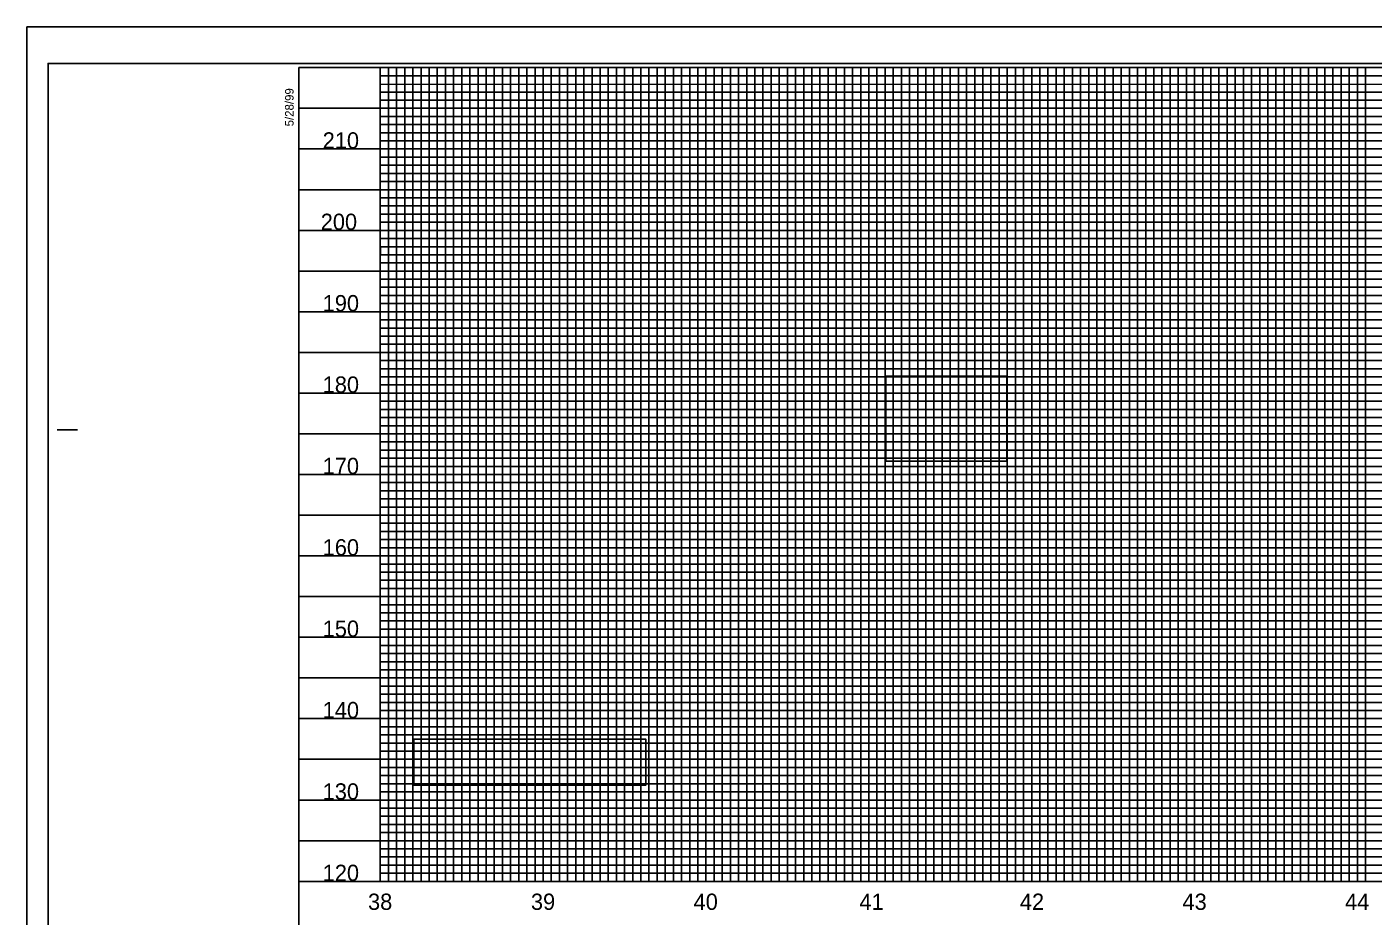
# Model space of a CAD drawing. Extents: x 1779926 to 1781610, y 620464 to 621564.
# Drawn here: x 1779926 to 1780753, y 621018 to 621564 of the extents above; entities that cross this region are included whole.
import ezdxf

# ---------------------------------------------------------------- set-up
doc = ezdxf.new("R2010")
doc.units = 0
for name, color, linetype in [('Exist Vertical Profile Horizontal Axis Label Major', 7, 'Continuous'), ('Exist Vertical Profile Vertical Axis Label', 7, 'Continuous'), ('Prop Grid Mask', 7, 'Continuous'), ('Scratch_Level_0', 7, 'Continuous'), ('Sheet Cutting Line CELL', 7, 'Continuous'), ('Sheet DOT Grid CELL', 7, 'Continuous'), ('Sheet Layout Profile Border Port 1', 7, 'Continuous'), ('Sheet Plot Border Inside CELL', 7, 'Continuous'), ('Sheet Plot Border Outside CELL', 7, 'Continuous'), ('Sheet Profile CELL', 7, 'Continuous'), ('Sheet Profile Grid Major CELL', 7, 'Continuous'), ('Sheet Profile Grid Middle CELL', 7, 'Continuous'), ('Sheet Profile Grid Minor CELL', 7, 'Continuous')]:
    doc.layers.add(name, color=color, linetype=linetype)

msp = doc.modelspace()

# ---------------------------------------------------------------- linework, layer by layer
at = {"layer": 'Prop Grid Mask'}
for points in [[(1780453.38, 621349.62), (1780527.67, 621349.62), (1780527.67, 621297.29), (1780453.38, 621297.29)], [(1780163.46, 621126.58), (1780305.99, 621126.58), (1780305.99, 621098.3), (1780163.46, 621098.3)]]:
    msp.add_lwpolyline(points, close=True, dxfattribs=at)
at = {"layer": 'Scratch_Level_0'}
msp.add_lwpolyline([(1780142.96, 621039.19), (1780142.96, 621539.19), (1781392.96, 621539.19), (1781392.96, 621314.19), (1781542.96, 621314.19), (1781542.96, 621039.19)], close=True, dxfattribs=at)
at = {"layer": 'Sheet Cutting Line CELL'}
for p, q in [((1781609.96, 621564.19), (1779925.96, 621564.19)), ((1779925.96, 621564.19), (1779925.96, 620464.19))]:
    msp.add_line(p, q, dxfattribs=at)
at = {"layer": 'Sheet DOT Grid CELL'}
for p, q in [((1780142.96, 621039.19), (1780142.96, 621539.19)), ((1780192.96, 621039.19), (1780192.96, 621539.19)), ((1780242.96, 621039.19), (1780242.96, 621539.19)), ((1780292.96, 621039.19), (1780292.96, 621539.19)), ((1780342.96, 621039.19), (1780342.96, 621539.19)), ((1780392.96, 621039.19), (1780392.96, 621539.19)), ((1780442.96, 621039.19), (1780442.96, 621539.19)), ((1780492.96, 621039.19), (1780492.96, 621539.19)), ((1780542.96, 621039.19), (1780542.96, 621539.19)), ((1780592.96, 621039.19), (1780592.96, 621539.19)), ((1780642.96, 621039.19), (1780642.96, 621539.19)), ((1780692.96, 621039.19), (1780692.96, 621539.19)), ((1780742.96, 621039.19), (1780742.96, 621539.19)), ((1781392.91, 621489.19), (1780092.96, 621489.19)), ((1781392.91, 621439.19), (1780092.96, 621439.19)), ((1781392.96, 621389.19), (1780092.96, 621389.19)), ((1781392.91, 621339.19), (1780092.96, 621339.19)), ((1781592.96, 621289.19), (1780092.96, 621289.19)), ((1781592.96, 621239.19), (1780092.96, 621239.19)), ((1781592.96, 621189.19), (1780092.96, 621189.19)), ((1781592.96, 621139.19), (1780092.96, 621139.19)), ((1781592.96, 621089.19), (1780092.96, 621089.19))]:
    msp.add_line(p, q, dxfattribs=at)
at = {"layer": 'Sheet Layout Profile Border Port 1'}
msp.add_lwpolyline([(1780142.96, 621378.14), (1780142.96, 621039.19), (1781542.96, 621039.19), (1781542.96, 621314.19)], dxfattribs=at)
at = {"layer": 'Sheet Plot Border Inside CELL'}
msp.add_lwpolyline([(1779938.96, 620486.64), (1781605.46, 620486.64), (1781605.46, 621541.74), (1779938.96, 621541.74)], close=True, dxfattribs=at)
at = {"layer": 'Sheet Plot Border Outside CELL'}
msp.add_lwpolyline([(1779925.96, 620464.19), (1781609.96, 620464.19), (1781609.96, 621564.19), (1779925.96, 621564.19)], close=True, dxfattribs=at)
at = {"layer": 'Sheet Profile CELL'}
for p, q in [((1779944.46, 621316.69), (1779956.96, 621316.69)), ((1780092.96, 621039.19), (1781592.96, 621039.19))]:
    msp.add_line(p, q, dxfattribs=at)
msp.add_lwpolyline([(1781592.96, 621539.19), (1780092.96, 621539.19), (1780092.96, 620489.19), (1781592.96, 620489.19)], close=True, dxfattribs=at)
at = {"layer": 'Sheet Profile Grid Major CELL'}
for points in [[(1780142.96, 621539.19), (1780142.96, 621039.19), (1780192.96, 621039.19), (1780192.96, 621539.19), (1780242.96, 621539.19), (1780242.96, 621039.19), (1780292.96, 621039.19), (1780292.96, 621539.19), (1780342.96, 621539.19), (1780342.96, 621039.19), (1780392.96, 621039.19), (1780392.96, 621539.19), (1780442.96, 621539.19), (1780442.96, 621039.19), (1780492.96, 621039.19), (1780492.96, 621539.19), (1780542.96, 621539.19), (1780542.96, 621039.19), (1780592.96, 621039.19), (1780592.96, 621539.19), (1780642.96, 621539.19), (1780642.96, 621039.19), (1780692.96, 621039.19), (1780692.96, 621539.19), (1780742.96, 621539.19), (1780742.96, 621039.19), (1780792.96, 621039.19)], [(1780092.96, 621489.19), (1781392.96, 621489.19)], [(1781392.96, 621439.19), (1780092.96, 621439.19), (1780092.96, 621389.19), (1781392.96, 621389.19)], [(1781392.91, 621339.19), (1780092.96, 621339.19), (1780092.96, 621289.19), (1781592.96, 621289.19)], [(1781592.96, 621239.19), (1780092.96, 621239.19), (1780092.96, 621189.19), (1781592.96, 621189.19)], [(1781592.96, 621139.19), (1780092.96, 621139.19), (1780092.96, 621139.19), (1780092.96, 621089.19), (1781592.96, 621089.19)]]:
    msp.add_lwpolyline(points, dxfattribs=at)
at = {"layer": 'Sheet Profile Grid Middle CELL'}
msp.add_line((1780092.96, 621514.19), (1781392.91, 621514.19), dxfattribs=at)
for points in [[(1780167.96, 621539.19), (1780167.96, 621039.19), (1780217.96, 621039.19), (1780217.96, 621539.19), (1780267.96, 621539.19), (1780267.96, 621039.19), (1780317.96, 621039.19), (1780317.96, 621539.19), (1780367.96, 621539.19), (1780367.96, 621039.19), (1780417.96, 621039.19), (1780417.96, 621539.19), (1780467.96, 621539.19), (1780467.96, 621039.19), (1780517.96, 621039.19), (1780517.96, 621539.19), (1780567.96, 621539.19), (1780567.96, 621039.19), (1780617.96, 621039.19), (1780617.96, 621539.19), (1780667.96, 621539.19), (1780667.96, 621039.19), (1780717.96, 621039.19), (1780717.96, 621039.19), (1780717.96, 621539.19), (1780767.96, 621539.19)], [(1781392.96, 621464.19), (1780092.96, 621464.19), (1780092.96, 621414.19), (1781392.96, 621414.19)], [(1781392.91, 621364.19), (1780092.96, 621364.19), (1780092.96, 621314.19), (1781417.96, 621314.19)], [(1781592.96, 621264.19), (1780092.96, 621264.19), (1780092.96, 621214.19), (1781592.96, 621214.19)], [(1781592.96, 621164.19), (1780092.96, 621164.19), (1780092.96, 621114.19), (1781592.96, 621114.19)], [(1781592.96, 621064.19), (1780092.96, 621064.19)]]:
    msp.add_lwpolyline(points, dxfattribs=at)
at = {"layer": 'Sheet Profile Grid Minor CELL'}
for p, q in [((1780142.96, 621534.19), (1781392.96, 621534.19)), ((1780142.96, 621529.19), (1780142.96, 621529.19)), ((1781392.96, 621529.19), (1780142.96, 621528.84)), ((1780142.96, 621524.19), (1781392.96, 621524.19)), ((1781392.91, 621404.19), (1780142.96, 621404.19)), ((1781392.96, 621399.19), (1780142.96, 621399.19)), ((1781392.96, 621394.19), (1780142.96, 621394.19)), ((1780142.96, 621384.19), (1781392.96, 621384.19)), ((1781392.96, 621379.19), (1780142.96, 621379.19)), ((1780142.96, 621374.19), (1781392.96, 621374.19)), ((1781392.96, 621354.19), (1780142.96, 621354.19)), ((1780142.96, 621349.19), (1781392.96, 621349.19)), ((1781392.91, 621329.19), (1780142.96, 621329.19)), ((1780142.96, 621324.19), (1781392.91, 621324.19)), ((1781542.96, 621304.19), (1780142.96, 621304.19)), ((1780142.96, 621299.19), (1781542.96, 621299.19)), ((1781542.96, 621294.19), (1780142.96, 621294.19)), ((1780142.96, 621284.19), (1781542.96, 621284.19)), ((1781542.96, 621279.19), (1780142.96, 621279.19)), ((1780142.96, 621274.19), (1781542.96, 621274.19)), ((1781542.96, 621269.19), (1780142.96, 621269.19)), ((1780142.96, 621259.19), (1781542.96, 621259.19)), ((1781542.96, 621254.19), (1780142.96, 621254.19)), ((1780142.96, 621249.19), (1781542.96, 621249.19)), ((1781542.96, 621244.19), (1780142.96, 621244.19)), ((1780142.96, 621234.19), (1781542.96, 621234.19)), ((1781542.96, 621229.19), (1780142.96, 621229.19)), ((1780142.96, 621224.19), (1781542.96, 621224.19)), ((1781542.96, 621219.19), (1780142.96, 621219.19)), ((1780142.96, 621209.19), (1781542.96, 621209.19)), ((1781542.96, 621204.19), (1780142.96, 621204.19)), ((1780142.96, 621199.19), (1781542.96, 621199.19)), ((1781542.96, 621194.19), (1780142.96, 621194.19)), ((1780142.96, 621184.19), (1781542.96, 621184.19)), ((1781542.96, 621179.19), (1780142.96, 621179.19)), ((1780142.96, 621174.19), (1781542.96, 621174.19)), ((1781542.96, 621169.19), (1780142.96, 621169.19)), ((1780142.96, 621159.19), (1781542.96, 621159.19)), ((1781542.96, 621154.19), (1780142.96, 621154.19)), ((1781542.96, 621149.19), (1780142.96, 621149.19)), ((1781542.96, 621144.19), (1780142.96, 621144.19)), ((1780142.96, 621134.19), (1781542.96, 621134.19)), ((1781542.96, 621129.19), (1780142.96, 621129.19)), ((1780142.96, 621124.19), (1781542.96, 621124.19)), ((1781542.96, 621119.19), (1780142.96, 621119.19)), ((1780142.96, 621109.19), (1781542.96, 621109.19)), ((1781542.96, 621104.19), (1780142.96, 621104.19)), ((1780142.96, 621099.19), (1781542.96, 621099.19)), ((1781542.96, 621094.19), (1780142.96, 621094.19)), ((1780142.96, 621084.19), (1781542.96, 621084.19)), ((1781542.96, 621079.19), (1780142.96, 621079.19)), ((1780142.96, 621074.19), (1781542.96, 621074.19)), ((1781542.96, 621069.19), (1780142.96, 621069.19)), ((1780142.96, 621059.19), (1781542.96, 621059.19)), ((1781542.96, 621054.19), (1780142.96, 621054.19)), ((1780142.96, 621049.19), (1781542.96, 621049.19))]:
    msp.add_line(p, q, dxfattribs=at)
for points in [[(1780147.96, 621539.19), (1780147.96, 621039.19), (1780152.96, 621039.19), (1780152.96, 621539.19), (1780157.96, 621539.19), (1780157.96, 621039.19), (1780162.96, 621039.19), (1780162.96, 621539.19), (1780172.96, 621539.19), (1780172.96, 621039.19), (1780177.96, 621039.19), (1780177.96, 621539.19), (1780182.96, 621539.19), (1780182.96, 621039.19), (1780187.96, 621039.19), (1780197.96, 621039.19), (1780202.96, 621039.19), (1780202.96, 621539.19), (1780207.96, 621539.19), (1780207.96, 621039.19), (1780212.96, 621039.19), (1780212.96, 621539.19), (1780222.96, 621539.19), (1780222.96, 621039.19), (1780227.96, 621039.19), (1780227.96, 621539.19), (1780232.96, 621539.19), (1780232.96, 621039.19), (1780237.96, 621039.19), (1780237.96, 621539.19), (1780247.96, 621539.19), (1780247.96, 621039.19), (1780252.96, 621039.19), (1780252.96, 621539.19), (1780257.96, 621539.19), (1780257.96, 621039.19), (1780262.96, 621039.19), (1780262.96, 621539.19), (1780272.96, 621539.19), (1780272.96, 621039.19), (1780277.96, 621039.19), (1780277.96, 621539.19), (1780282.96, 621539.19), (1780282.96, 621039.19), (1780287.96, 621039.19), (1780287.96, 621539.19), (1780297.96, 621539.19), (1780297.96, 621039.19), (1780302.96, 621039.19), (1780302.96, 621539.19), (1780307.96, 621539.19), (1780307.96, 621039.19), (1780312.96, 621039.19), (1780312.96, 621539.19), (1780322.96, 621539.19), (1780322.96, 621039.19), (1780327.96, 621039.19), (1780327.96, 621539.19), (1780332.96, 621539.19), (1780332.96, 621039.19), (1780337.96, 621039.19), (1780337.96, 621539.19), (1780347.96, 621539.19), (1780347.96, 621039.19), (1780352.96, 621039.19), (1780352.96, 621539.19), (1780357.96, 621539.19), (1780357.96, 621039.19)], [(1780187.96, 621039.19), (1780187.96, 621539.19), (1780197.96, 621539.19), (1780197.96, 621039.19)], [(1780357.96, 621039.19), (1780362.96, 621039.19), (1780362.96, 621539.19), (1780372.96, 621539.19), (1780372.96, 621039.19), (1780377.96, 621039.19), (1780377.96, 621539.19), (1780382.96, 621539.19), (1780382.96, 621039.19), (1780387.96, 621039.19), (1780387.96, 621539.19), (1780397.96, 621539.19), (1780397.96, 621039.19), (1780402.96, 621039.19), (1780402.96, 621539.19), (1780407.96, 621539.19), (1780407.96, 621039.19), (1780412.96, 621039.19), (1780412.96, 621539.19), (1780422.96, 621539.19), (1780422.96, 621039.19), (1780427.96, 621039.19), (1780427.96, 621539.19), (1780432.96, 621539.19), (1780432.96, 621039.19), (1780437.96, 621039.19), (1780437.96, 621539.19), (1780447.96, 621539.19), (1780447.96, 621039.19), (1780452.96, 621039.19), (1780452.96, 621539.19), (1780457.96, 621539.19), (1780457.96, 621039.19), (1780462.96, 621039.19), (1780462.96, 621539.19), (1780472.96, 621539.19), (1780472.96, 621039.19), (1780477.96, 621039.19), (1780477.96, 621539.19), (1780482.96, 621539.19), (1780482.96, 621039.19), (1780487.96, 621039.19), (1780487.96, 621539.19), (1780497.96, 621539.19), (1780497.96, 621039.19), (1780502.96, 621039.19), (1780502.96, 621539.19), (1780507.96, 621539.19), (1780507.96, 621039.19), (1780512.96, 621039.19), (1780512.96, 621539.19), (1780522.96, 621539.19), (1780522.96, 621039.19), (1780527.96, 621039.19), (1780527.96, 621539.19), (1780532.96, 621539.19), (1780532.96, 621039.19), (1780537.96, 621039.19), (1780537.96, 621539.19), (1780547.96, 621539.19), (1780547.96, 621039.19), (1780552.96, 621039.19), (1780552.96, 621539.19), (1780557.96, 621539.19), (1780557.96, 621039.19), (1780562.96, 621039.19), (1780562.96, 621539.19), (1780572.96, 621539.19), (1780572.96, 621039.19), (1780577.96, 621039.19), (1780577.96, 621539.19), (1780582.96, 621539.19), (1780582.96, 621039.19), (1780587.96, 621039.19), (1780587.96, 621539.19), (1780597.96, 621539.19), (1780597.96, 621039.19), (1780602.96, 621039.19), (1780602.96, 621539.19), (1780607.96, 621539.19), (1780607.96, 621039.19), (1780612.96, 621039.19), (1780612.96, 621539.19), (1780622.96, 621539.19), (1780622.96, 621039.19), (1780627.96, 621039.19), (1780627.96, 621539.19), (1780632.96, 621539.19), (1780632.96, 621039.19), (1780637.96, 621039.19), (1780637.96, 621539.19), (1780647.96, 621539.19), (1780647.96, 621039.19), (1780652.96, 621039.19), (1780652.96, 621539.19), (1780657.96, 621539.19), (1780657.96, 621039.19), (1780662.96, 621039.19), (1780662.96, 621539.19), (1780672.96, 621539.19)], [(1780672.96, 621539.19), (1780672.96, 621039.19), (1780677.96, 621039.19), (1780677.96, 621539.19), (1780682.96, 621539.19), (1780682.96, 621039.19), (1780687.96, 621039.19), (1780687.96, 621539.19), (1780697.96, 621539.19), (1780697.96, 621039.19), (1780702.96, 621039.19), (1780702.96, 621539.19), (1780707.96, 621539.19), (1780707.96, 621039.19), (1780712.96, 621039.19), (1780712.96, 621539.19), (1780722.96, 621539.19), (1780722.96, 621039.19), (1780727.96, 621039.19), (1780727.96, 621539.19), (1780732.96, 621539.19), (1780732.96, 621039.19), (1780737.96, 621039.19), (1780737.96, 621539.19), (1780747.96, 621539.19), (1780747.96, 621039.19), (1780752.96, 621039.19)], [(1781392.96, 621519.19), (1780142.96, 621519.19), (1780142.96, 621509.19), (1781392.96, 621509.19)], [(1781392.91, 621504.19), (1780142.96, 621504.19), (1780142.96, 621499.19), (1781392.96, 621499.19)], [(1781392.96, 621494.19), (1780142.96, 621494.19), (1780142.96, 621484.19), (1781392.96, 621484.19)], [(1781392.96, 621479.19), (1780142.96, 621479.19), (1780142.96, 621474.19), (1781392.96, 621474.19)], [(1781392.96, 621469.19), (1780142.96, 621469.19), (1780142.96, 621459.19), (1781392.96, 621459.19)], [(1781392.96, 621454.19), (1780142.96, 621454.19), (1780142.96, 621449.19), (1781392.96, 621449.19)], [(1781392.96, 621444.19), (1780142.96, 621444.19), (1780142.96, 621434.19), (1781392.96, 621434.19)], [(1781392.96, 621429.09), (1780143.06, 621429.09), (1780143.06, 621424.19), (1781392.96, 621424.19)], [(1781392.96, 621419.19), (1780142.96, 621419.19), (1780142.96, 621409.19), (1781392.96, 621409.19)], [(1781392.91, 621369.19), (1780142.96, 621369.19), (1780142.96, 621359.19), (1781392.91, 621359.19)], [(1781392.91, 621344.19), (1780142.96, 621344.19), (1780142.96, 621334.19), (1781392.91, 621334.19)], [(1781392.91, 621319.19), (1780142.96, 621319.19), (1780142.96, 621309.19), (1781542.96, 621309.19)], [(1781542.96, 621044.19), (1780142.96, 621044.19)]]:
    msp.add_lwpolyline(points, dxfattribs=at)

# ---------------------------------------------------------------- texts
at = {"layer": 'Exist Vertical Profile Horizontal Axis Label Major'}
for s, p in [('38', (1780135.43, 621021.69)), ('39', (1780235.47, 621021.69)), ('40', (1780335.35, 621021.69)), ('41', (1780437.19, 621021.69)), ('42', (1780535.73, 621021.69)), ('43', (1780635.57, 621021.69)), ('44', (1780735.41, 621021.69))]:
    msp.add_text(s, height=10, dxfattribs=at).set_placement(p)
at = {"layer": 'Exist Vertical Profile Vertical Axis Label'}
for s, p in [('210', (1780107.59, 621489.44)), ('200', (1780106.39, 621439.44)), ('190', (1780107.59, 621389.44)), ('180', (1780107.59, 621339.44)), ('170', (1780107.59, 621289.44)), ('160', (1780107.59, 621239.44)), ('150', (1780107.59, 621189.44)), ('140', (1780107.59, 621139.44)), ('130', (1780107.59, 621089.44)), ('120', (1780107.59, 621039.44))]:
    msp.add_text(s, height=10, dxfattribs=at).set_placement(p)
at = {"layer": 'Sheet Profile CELL'}
msp.add_text('5/28/99', height=5.25, rotation=90, dxfattribs=at).set_placement((1780089.72, 621503.1))

doc.saveas('drawing.dxf')
